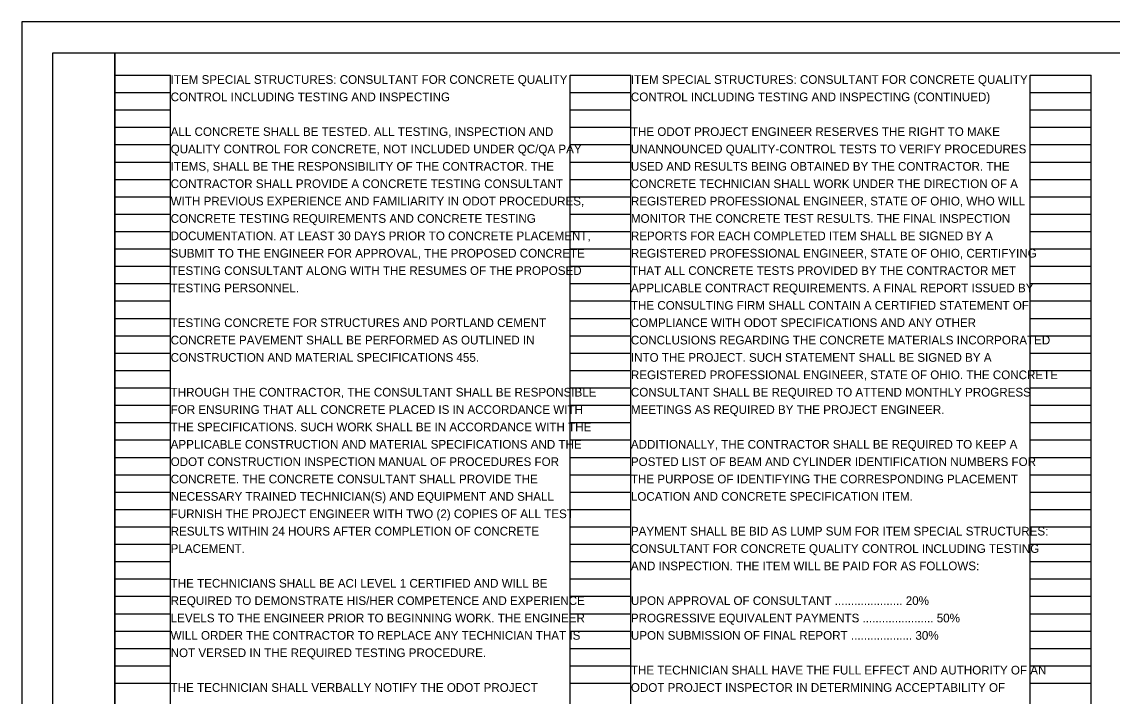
# Model space of a CAD drawing. Extents: x 0 to 34, y 0 to 22.
# Drawn here: x 0 to 17.58, y 11.13 to 22 of the extents above; entities that cross this region are included whole.
import ezdxf

# ---------------------------------------------------------------- set-up
doc = ezdxf.new("R2010")
doc.units = 0
for name, color, linetype in [('Default', 7, 'Continuous'), ('SH_Border', 7, 'Continuous'), ('SH_Cut_Line', 7, 'Continuous'), ('SH_Data', 7, 'Continuous')]:
    doc.layers.add(name, color=color, linetype=linetype)

msp = doc.modelspace()

# ---------------------------------------------------------------- linework, layer by layer
at = {"layer": 'SH_Border'}
for points in [[(0.5, 21.5), (1.5, 21.5), (1.5, 0.5), (0.5, 0.5)], [(1.5, 21.5), (33.5, 21.5), (33.5, 0.5), (1.5, 0.5)]]:
    msp.add_lwpolyline(points, close=True, dxfattribs=at)
at = {"layer": 'SH_Cut_Line'}
msp.add_lwpolyline([(0, 0), (34, 0), (34, 22), (0, 22)], close=True, dxfattribs=at)
at = {"layer": 'SH_Data'}
for p, q in [((1.5, 0.98), (1.5, 21.14)), ((1.5, 21.14), (2.4, 21.14)), ((2.4, 0.98), (2.4, 21.14)), ((8.84, 0.98), (8.84, 21.14)), ((8.84, 21.14), (9.82, 21.14)), ((9.82, 0.98), (9.82, 21.14)), ((16.26, 0.98), (16.26, 21.14)), ((16.26, 21.14), (17.24, 21.14)), ((17.24, 0.98), (17.24, 21.14)), ((1.5, 20.86), (2.4, 20.86)), ((8.84, 20.86), (9.82, 20.86)), ((16.26, 20.86), (17.24, 20.86)), ((1.5, 20.58), (2.4, 20.58)), ((8.84, 20.58), (9.82, 20.58)), ((16.26, 20.58), (17.24, 20.58)), ((1.5, 20.3), (2.4, 20.3)), ((8.84, 20.3), (9.82, 20.3)), ((16.26, 20.3), (17.24, 20.3)), ((1.5, 20.02), (2.4, 20.02)), ((8.84, 20.02), (9.82, 20.02)), ((16.26, 20.02), (17.24, 20.02)), ((1.5, 19.74), (2.4, 19.74)), ((8.84, 19.74), (9.82, 19.74)), ((16.26, 19.74), (17.24, 19.74)), ((1.5, 19.46), (2.4, 19.46)), ((8.84, 19.46), (9.82, 19.46)), ((16.26, 19.46), (17.24, 19.46)), ((1.5, 19.18), (2.4, 19.18)), ((8.84, 19.18), (9.82, 19.18)), ((16.26, 19.18), (17.24, 19.18)), ((1.5, 18.9), (2.4, 18.9)), ((8.84, 18.9), (9.82, 18.9)), ((16.26, 18.9), (17.24, 18.9)), ((1.5, 18.62), (2.4, 18.62)), ((8.84, 18.62), (9.82, 18.62)), ((16.26, 18.62), (17.24, 18.62)), ((1.5, 18.34), (2.4, 18.34)), ((8.84, 18.34), (9.82, 18.34)), ((16.26, 18.34), (17.24, 18.34)), ((1.5, 18.06), (2.4, 18.06)), ((8.84, 18.06), (9.82, 18.06)), ((16.26, 18.06), (17.24, 18.06)), ((1.5, 17.78), (2.4, 17.78)), ((8.84, 17.78), (9.82, 17.78)), ((16.26, 17.78), (17.24, 17.78)), ((1.5, 17.5), (2.4, 17.5)), ((8.84, 17.5), (9.82, 17.5)), ((16.26, 17.5), (17.24, 17.5)), ((1.5, 17.22), (2.4, 17.22)), ((8.84, 17.22), (9.82, 17.22)), ((16.26, 17.22), (17.24, 17.22)), ((1.5, 16.94), (2.4, 16.94)), ((8.84, 16.94), (9.82, 16.94)), ((16.26, 16.94), (17.24, 16.94)), ((1.5, 16.66), (2.4, 16.66)), ((8.84, 16.66), (9.82, 16.66)), ((16.26, 16.66), (17.24, 16.66)), ((1.5, 16.38), (2.4, 16.38)), ((8.84, 16.38), (9.82, 16.38)), ((16.26, 16.38), (17.24, 16.38)), ((1.5, 16.1), (2.4, 16.1)), ((8.84, 16.1), (9.82, 16.1)), ((16.26, 16.1), (17.24, 16.1)), ((1.5, 15.82), (2.4, 15.82)), ((8.84, 15.82), (9.82, 15.82)), ((16.26, 15.82), (17.24, 15.82)), ((1.5, 15.54), (2.4, 15.54)), ((8.84, 15.54), (9.82, 15.54)), ((16.26, 15.54), (17.24, 15.54)), ((1.5, 15.26), (2.4, 15.26)), ((8.84, 15.26), (9.82, 15.26)), ((16.26, 15.26), (17.24, 15.26)), ((1.5, 14.98), (2.4, 14.98)), ((8.84, 14.98), (9.82, 14.98)), ((16.26, 14.98), (17.24, 14.98)), ((1.5, 14.7), (2.4, 14.7)), ((8.84, 14.7), (9.82, 14.7)), ((16.26, 14.7), (17.24, 14.7)), ((1.5, 14.42), (2.4, 14.42)), ((8.84, 14.42), (9.82, 14.42)), ((16.26, 14.42), (17.24, 14.42)), ((1.5, 14.14), (2.4, 14.14)), ((8.84, 14.14), (9.82, 14.14)), ((16.26, 14.14), (17.24, 14.14)), ((1.5, 13.86), (2.4, 13.86)), ((8.84, 13.86), (9.82, 13.86)), ((16.26, 13.86), (17.24, 13.86)), ((1.5, 13.58), (2.4, 13.58)), ((8.84, 13.58), (9.82, 13.58)), ((16.26, 13.58), (17.24, 13.58)), ((1.5, 13.3), (2.4, 13.3)), ((8.84, 13.3), (9.82, 13.3)), ((16.26, 13.3), (17.24, 13.3)), ((1.5, 13.02), (2.4, 13.02)), ((8.84, 13.02), (9.82, 13.02)), ((16.26, 13.02), (17.24, 13.02)), ((1.5, 12.74), (2.4, 12.74)), ((8.84, 12.74), (9.82, 12.74)), ((16.26, 12.74), (17.24, 12.74)), ((1.5, 12.46), (2.4, 12.46)), ((8.84, 12.46), (9.82, 12.46)), ((16.26, 12.46), (17.24, 12.46)), ((1.5, 12.18), (2.4, 12.18)), ((8.84, 12.18), (9.82, 12.18)), ((16.26, 12.18), (17.24, 12.18)), ((1.5, 11.9), (2.4, 11.9)), ((8.84, 11.9), (9.82, 11.9)), ((16.26, 11.9), (17.24, 11.9)), ((1.5, 11.62), (2.4, 11.62)), ((8.84, 11.62), (9.82, 11.62)), ((16.26, 11.62), (17.24, 11.62)), ((1.5, 11.34), (2.4, 11.34)), ((8.84, 11.34), (9.82, 11.34)), ((16.26, 11.34), (17.24, 11.34))]:
    msp.add_line(p, q, dxfattribs=at)

# ---------------------------------------------------------------- texts
at = {"layer": 'Default'}
for s, p in [('ITEM SPECIAL STRUCTURES: CONSULTANT FOR CONCRETE QUALITY ', (2.4, 21)), ('ITEM SPECIAL STRUCTURES: CONSULTANT FOR CONCRETE QUALITY ', (9.82, 21)), ('CONTROL INCLUDING TESTING AND INSPECTING', (2.4, 20.72)), ('CONTROL INCLUDING TESTING AND INSPECTING (CONTINUED)', (9.82, 20.72)), ('ALL CONCRETE SHALL BE TESTED. ALL TESTING, INSPECTION AND ', (2.4, 20.16)), ('THE ODOT PROJECT ENGINEER RESERVES THE RIGHT TO MAKE ', (9.82, 20.16)), ('QUALITY CONTROL FOR CONCRETE, NOT INCLUDED UNDER QC/QA PAY ', (2.4, 19.88)), ('UNANNOUNCED QUALITY-CONTROL TESTS TO VERIFY PROCEDURES ', (9.82, 19.88)), ('ITEMS, SHALL BE THE RESPONSIBILITY OF THE CONTRACTOR. THE ', (2.4, 19.6)), ('USED AND RESULTS BEING OBTAINED BY THE CONTRACTOR. THE ', (9.82, 19.6)), ('CONTRACTOR SHALL PROVIDE A CONCRETE TESTING CONSULTANT ', (2.4, 19.32)), ('CONCRETE TECHNICIAN SHALL WORK UNDER THE DIRECTION OF A ', (9.82, 19.32)), ('WITH PREVIOUS EXPERIENCE AND FAMILIARITY IN ODOT PROCEDURES, ', (2.4, 19.04)), ('REGISTERED PROFESSIONAL ENGINEER, STATE OF OHIO, WHO WILL ', (9.82, 19.04)), ('CONCRETE TESTING REQUIREMENTS AND CONCRETE TESTING ', (2.4, 18.76)), ('MONITOR THE CONCRETE TEST RESULTS. THE FINAL INSPECTION ', (9.82, 18.76)), ('DOCUMENTATION. AT LEAST 30 DAYS PRIOR TO CONCRETE PLACEMENT, ', (2.4, 18.48)), ('REPORTS FOR EACH COMPLETED ITEM SHALL BE SIGNED BY A ', (9.82, 18.48)), ('SUBMIT TO THE ENGINEER FOR APPROVAL, THE PROPOSED CONCRETE ', (2.4, 18.2)), ('REGISTERED PROFESSIONAL ENGINEER, STATE OF OHIO, CERTIFYING ', (9.82, 18.2)), ('TESTING CONSULTANT ALONG WITH THE RESUMES OF THE PROPOSED ', (2.4, 17.92)), ('THAT ALL CONCRETE TESTS PROVIDED BY THE CONTRACTOR MET', (9.82, 17.92)), ('TESTING PERSONNEL.', (2.4, 17.64)), ('APPLICABLE CONTRACT REQUIREMENTS. A FINAL REPORT ISSUED BY ', (9.82, 17.64)), ('THE CONSULTING FIRM SHALL CONTAIN A CERTIFIED STATEMENT OF ', (9.82, 17.36)), ('TESTING CONCRETE FOR STRUCTURES AND PORTLAND CEMENT ', (2.4, 17.08)), ('COMPLIANCE WITH ODOT SPECIFICATIONS AND ANY OTHER ', (9.82, 17.08)), ('CONCRETE PAVEMENT SHALL BE PERFORMED AS OUTLINED IN ', (2.4, 16.8)), ('CONCLUSIONS REGARDING THE CONCRETE MATERIALS INCORPORATED ', (9.82, 16.8)), ('CONSTRUCTION AND MATERIAL SPECIFICATIONS 455.', (2.4, 16.52)), ('INTO THE PROJECT. SUCH STATEMENT SHALL BE SIGNED BY A', (9.82, 16.52)), ('REGISTERED PROFESSIONAL ENGINEER, STATE OF OHIO. THE CONCRETE ', (9.82, 16.24)), ('THROUGH THE CONTRACTOR, THE CONSULTANT SHALL BE RESPONSIBLE ', (2.4, 15.96)), ('CONSULTANT SHALL BE REQUIRED TO ATTEND MONTHLY PROGRESS ', (9.82, 15.96)), ('FOR ENSURING THAT ALL CONCRETE PLACED IS IN ACCORDANCE WITH ', (2.4, 15.68)), ('MEETINGS AS REQUIRED BY THE PROJECT ENGINEER.', (9.82, 15.68)), ('THE SPECIFICATIONS. SUCH WORK SHALL BE IN ACCORDANCE WITH THE ', (2.4, 15.4)), ('APPLICABLE CONSTRUCTION AND MATERIAL SPECIFICATIONS AND THE', (2.4, 15.12)), ('ADDITIONALLY, THE CONTRACTOR SHALL BE REQUIRED TO KEEP A ', (9.82, 15.12)), ('ODOT CONSTRUCTION INSPECTION MANUAL OF PROCEDURES FOR ', (2.4, 14.84)), ('POSTED LIST OF BEAM AND CYLINDER IDENTIFICATION NUMBERS FOR ', (9.82, 14.84)), ('CONCRETE. THE CONCRETE CONSULTANT SHALL PROVIDE THE ', (2.4, 14.56)), ('THE PURPOSE OF IDENTIFYING THE CORRESPONDING PLACEMENT ', (9.82, 14.56)), ('NECESSARY TRAINED TECHNICIAN(S) AND EQUIPMENT AND SHALL ', (2.4, 14.28)), ('LOCATION AND CONCRETE SPECIFICATION ITEM.', (9.82, 14.28)), ('FURNISH THE PROJECT ENGINEER WITH TWO (2) COPIES OF ALL TEST ', (2.4, 14)), ('RESULTS WITHIN 24 HOURS AFTER COMPLETION OF CONCRETE ', (2.4, 13.72)), ('PAYMENT SHALL BE BID AS LUMP SUM FOR ITEM SPECIAL STRUCTURES:', (9.82, 13.72)), ('PLACEMENT.', (2.4, 13.44)), ('CONSULTANT FOR CONCRETE QUALITY CONTROL INCLUDING TESTING ', (9.82, 13.44)), ('AND INSPECTION. THE ITEM WILL BE PAID FOR AS FOLLOWS:', (9.82, 13.16)), ('THE TECHNICIANS SHALL BE ACI LEVEL 1 CERTIFIED AND WILL BE ', (2.4, 12.88)), ('REQUIRED TO DEMONSTRATE HIS/HER COMPETENCE AND EXPERIENCE ', (2.4, 12.6)), ('UPON APPROVAL OF CONSULTANT ..................... 20%', (9.82, 12.6)), ('LEVELS TO THE ENGINEER PRIOR TO BEGINNING WORK. THE ENGINEER ', (2.4, 12.32)), ('PROGRESSIVE EQUIVALENT PAYMENTS ...................... 50%', (9.82, 12.32)), ('WILL ORDER THE CONTRACTOR TO REPLACE ANY TECHNICIAN THAT IS ', (2.4, 12.04)), ('UPON SUBMISSION OF FINAL REPORT ................... 30%', (9.82, 12.04)), ('NOT VERSED IN THE REQUIRED TESTING PROCEDURE.', (2.4, 11.76)), ('THE TECHNICIAN SHALL HAVE THE FULL EFFECT AND AUTHORITY OF AN ', (9.82, 11.48)), ('THE TECHNICIAN SHALL VERBALLY NOTIFY THE ODOT PROJECT ', (2.4, 11.2)), ('ODOT PROJECT INSPECTOR IN DETERMINING ACCEPTABILITY OF ', (9.82, 11.2))]:
    msp.add_text(s, height=0.14, dxfattribs=at).set_placement(p)

doc.saveas('drawing.dxf')
